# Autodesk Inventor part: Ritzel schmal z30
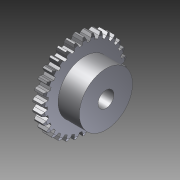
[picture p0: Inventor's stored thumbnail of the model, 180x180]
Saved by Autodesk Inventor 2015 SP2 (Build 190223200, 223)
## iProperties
Created: 2015-08
Part Number: Ritzel schmal z30
Material: Messing, weicher Gelbton
Document SubType Name: Modeling
Designer: ryll
Mass: 5.2489 g
Surface Area: 6.86122 cm^2
Volume: 0.619705 cm^3
Density: 8.47 g/cm^3
Appearance: Messing - satiniert
Title: c:/PPEXPORT/antriebselemente_und_normteile/stirnzahnraeder/stirnzahnraeder_messing/artikel_nr___26103000.stp
Creation Date: 2007-11-07
Author: ryll
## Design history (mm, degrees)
node "261030001"
node "1"
node "Basis1"
